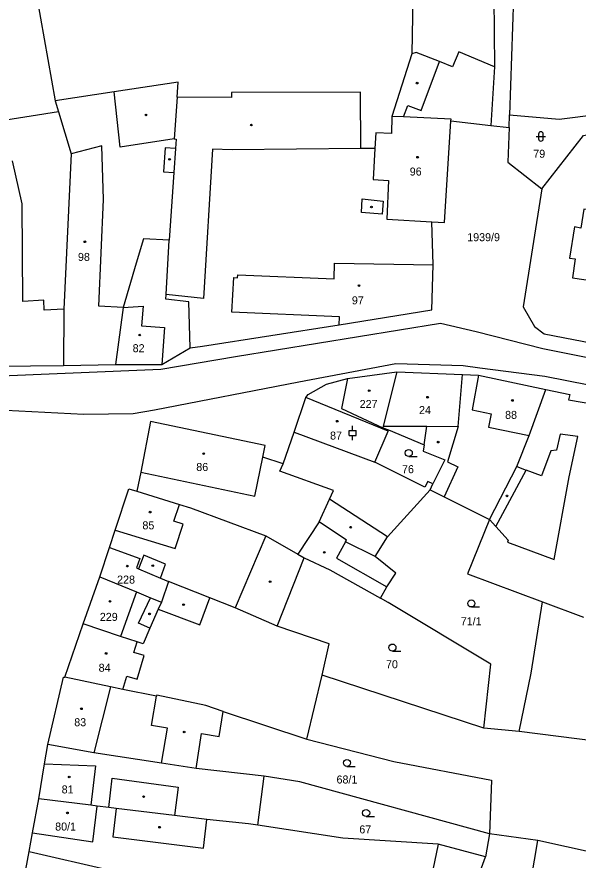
# Model space of a CAD drawing. Extents: x -794765 to -785424, y -1118958 to -1108731.
# Drawn here: x -788215.5 to -788096.4, y -1116478.9 to -1116299.9 of the extents above; entities that cross this region are included whole.
import ezdxf

# ---------------------------------------------------------------- set-up
doc = ezdxf.new("R2010")
doc.units = 0
for name, color, linetype in [('Level 66', 7, 'Continuous'), ('Level 75', 7, 'Continuous'), ('Level 76', 7, 'Continuous'), ('Level 77', 7, 'Continuous'), ('Level 79', 7, 'Continuous')]:
    doc.layers.add(name, color=color, linetype=linetype)

msp = doc.modelspace()

# ---------------------------------------------------------------- linework, layer by layer
at = {"layer": 'Level 66'}
for p, q in [((-788104.81, -1116324.75), (-788104.81, -1116325.75)), ((-788103.81, -1116325.75), (-788103.81, -1116324.75)), ((-788105.31, -1116325.25), (-788103.31, -1116325.25)), ((-788144.27, -1116387.72), (-788144.27, -1116386.72)), ((-788145.02, -1116387.72), (-788143.52, -1116387.72)), ((-788145.02, -1116388.72), (-788145.02, -1116387.72)), ((-788145.02, -1116388.72), (-788143.52, -1116388.72)), ((-788144.27, -1116389.72), (-788144.27, -1116388.72)), ((-788143.52, -1116388.72), (-788143.52, -1116387.72)), ((-788132.34, -1116393.21), (-788130.59, -1116393.21)), ((-788119.06, -1116425.15), (-788117.31, -1116425.15)), ((-788135.81, -1116434.52), (-788134.06, -1116434.52)), ((-788145.46, -1116459.02), (-788143.71, -1116459.02)), ((-788141.39, -1116469.65), (-788139.64, -1116469.65))]:
    msp.add_line(p, q, dxfattribs=at)
for centre in [(-788132.34, -1116392.46), (-788119.06, -1116424.4), (-788135.81, -1116433.77), (-788145.46, -1116458.27), (-788141.39, -1116468.9)]:
    msp.add_circle(centre, 0.75, dxfattribs=at)
for centre, start, end in [((-788104.31, -1116324.75), 0, 180), ((-788104.31, -1116325.75), 180, 359.9879)]:
    msp.add_arc(centre, 0.5, start, end, dxfattribs=at)
at = {"layer": 'Level 75'}
for p, q in [((-788109.43, -1116275.32), (-788110.98, -1116320.69)), ((-788214.62, -1116276.87), (-788207.41, -1116317.68)), ((-788131.16, -1116277.26), (-788131.71, -1116307.69)), ((-788114.43, -1116279.33), (-788114.17, -1116310.48)), ((-788114.17, -1116310.48), (-788114.92, -1116322.89)), ((-788207.41, -1116317.68), (-788206.71, -1116320.02)), ((-788206.71, -1116320.02), (-788223.3, -1116322.65)), ((-788111.07, -1116323.34), (-788110.98, -1116320.69)), ((-788114.92, -1116322.89), (-788111.07, -1116323.34)), ((-788222.28, -1116374.04), (-788205.6, -1116373.91)), ((-788205.6, -1116373.91), (-788194.63, -1116373.69)), ((-788134.88, -1116375.26), (-788120.97, -1116375.78)), ((-788136.75, -1116387.84), (-788154.18, -1116380.69)), ((-788136.75, -1116387.84), (-788136.64, -1116387.57)), ((-788136.64, -1116387.57), (-788129.09, -1116390.72)), ((-788127.83, -1116400.27), (-788127.21, -1116399.02)), ((-788197.94, -1116418.79), (-788195.87, -1116412.55)), ((-788160.3, -1116429.24), (-788154.54, -1116414.71)), ((-788201.48, -1116428.76), (-788197.94, -1116418.79)), ((-788183.36, -1116419.76), (-788184.84, -1116424.13)), ((-788103.93, -1116424.04), (-788095.26, -1116427.29)), ((-788205.35, -1116440.07), (-788201.48, -1116428.76)), ((-788153.97, -1116453.21), (-788150.71, -1116439.67)), ((-788116.43, -1116450.89), (-788150.71, -1116439.67)), ((-788171.76, -1116447.38), (-788153.97, -1116453.21)), ((-788108.88, -1116451.59), (-788116.43, -1116450.89)), ((-788070.15, -1116456.47), (-788108.88, -1116451.59)), ((-788163.01, -1116461.06), (-788177.5, -1116459.45)), ((-788164.41, -1116471.51), (-788163.01, -1116461.06)), ((-788115.24, -1116473.36), (-788116.05, -1116478.24)), ((-788104.94, -1116474.74), (-788115.24, -1116473.36)), ((-788109.95, -1116503.68), (-788104.94, -1116474.74)), ((-788116.05, -1116478.24), (-788126.07, -1116475.51)), ((-788120.85, -1116491.06), (-788116.05, -1116478.24))]:
    msp.add_line(p, q, dxfattribs=at)
for points in [[(-788131.71, -1116307.69), (-788135.94, -1116321), (-788135.99, -1116324.59), (-788139.33, -1116324.46), (-788139.53, -1116327.84)], [(-788114.17, -1116310.48), (-788121.75, -1116307.28), (-788123.04, -1116310.44), (-788125.79, -1116309.36), (-788130.81, -1116307.4), (-788131.71, -1116307.69)], [(-788181.52, -1116316.94), (-788181.29, -1116313.7), (-788194.86, -1116315.77), (-788207.41, -1116317.68)], [(-788181.52, -1116316.94), (-788182.17, -1116325.75), (-788181.73, -1116325.82), (-788181.87, -1116327.84), (-788182.21, -1116332.88), (-788183.18, -1116347.24)], [(-788139.53, -1116327.84), (-788142.54, -1116327.81), (-788142.59, -1116315.86), (-788169.99, -1116315.9), (-788169.98, -1116316.98), (-788181.52, -1116316.94)], [(-788206.71, -1116320.02), (-788204, -1116328.92), (-788205.54, -1116361.89), (-788205.6, -1116373.91)], [(-788110.98, -1116320.69), (-788100.4, -1116321.61), (-788083.57, -1116319.47), (-788043.34, -1116329.62), (-788043.51, -1116333.19)], [(-788127.43, -1116343.38), (-788124.74, -1116343.55), (-788123.4, -1116321.9), (-788114.92, -1116322.89)], [(-788104.08, -1116336.38), (-788095.27, -1116325.08), (-788084.6, -1116322.77), (-788075.84, -1116324.92), (-788043.51, -1116333.19)], [(-788111.07, -1116323.34), (-788111.32, -1116330.72), (-788104.08, -1116336.38)], [(-788139.53, -1116327.84), (-788139.9, -1116334.41), (-788136.65, -1116334.6), (-788137.01, -1116342.78), (-788127.43, -1116343.38)], [(-788104.08, -1116336.38), (-788108.05, -1116361.45), (-788105.63, -1116365.59), (-788103.61, -1116367.18), (-788046.1, -1116378.3), (-788038.81, -1116378.46), (-788035.35, -1116378.54), (-788022.85, -1116378.83), (-788020.59, -1116378.86)], [(-788065.34, -1116346.88), (-788064.86, -1116342.89), (-788072.76, -1116341.74), (-788073.06, -1116343.77), (-788095.19, -1116340.68), (-788095.84, -1116344.71), (-788097.16, -1116344.45), (-788098.21, -1116351.08), (-788097, -1116351.26), (-788097.58, -1116355.3), (-788075.44, -1116358.49), (-788075.73, -1116360.48), (-788067.47, -1116361.8), (-788066.97, -1116357.98)], [(-788178.72, -1116370.15), (-788176.14, -1116369.75), (-788147.1, -1116365.24), (-788127.46, -1116362.08), (-788127.18, -1116352.49), (-788127.43, -1116343.38)], [(-788183.18, -1116347.24), (-788188.64, -1116346.96), (-788190.2, -1116352.14), (-788192.99, -1116361.57), (-788194.63, -1116373.69)], [(-788178.72, -1116370.15), (-788179.03, -1116360.37), (-788183.89, -1116359.83), (-788183.83, -1116358.84), (-788183.18, -1116347.24)], [(-788279.68, -1116369.68), (-788255.51, -1116372.91), (-788222.27, -1116376.2), (-788184.96, -1116374.64), (-788169.09, -1116371.97), (-788125.59, -1116364.93), (-788118.03, -1116366.65), (-788103.88, -1116370.26), (-788071.66, -1116376.73), (-788047.19, -1116381.42), (-788037.25, -1116382.67), (-788028.44, -1116382.62), (-788012.56, -1116381.23), (-787982.57, -1116375.12), (-787957.81, -1116369.21), (-787938.9, -1116364.93), (-787918.57, -1116359.78), (-787902.51, -1116353.37)], [(-788194.63, -1116373.69), (-788184.79, -1116373.64), (-788178.72, -1116370.15)], [(-788014.95, -1116388.89), (-788036.64, -1116389.18), (-788070.79, -1116382.68), (-788103.44, -1116376.2), (-788117.24, -1116374.47), (-788120.83, -1116373.97), (-788135.12, -1116373.51), (-788155.68, -1116377.39), (-788186.34, -1116383.39), (-788190.87, -1116384.17), (-788201.33, -1116384.26), (-788234.5, -1116382.6)], [(-788154.18, -1116380.69), (-788153.72, -1116380.03), (-788149.81, -1116377.84), (-788145.34, -1116376.64), (-788134.88, -1116375.26)], [(-788134.88, -1116375.26), (-788137.77, -1116386.76), (-788137.87, -1116387.15), (-788136.64, -1116387.57)], [(-788129.09, -1116390.72), (-788128.51, -1116386.8), (-788121.84, -1116386.83), (-788120.97, -1116375.78)], [(-788120.97, -1116375.78), (-788117.53, -1116375.94), (-788103.27, -1116378.99)], [(-788115.23, -1116406.59), (-788109.4, -1116395.34), (-788106.8, -1116388.75), (-788103.27, -1116378.99)], [(-788103.27, -1116378.99), (-788098.18, -1116380.06), (-788098.42, -1116381.18), (-788087.66, -1116383.04)], [(-788158.98, -1116394.77), (-788156.67, -1116388.02), (-788154.18, -1116380.69)], [(-788158.98, -1116394.77), (-788163.35, -1116393.38), (-788162.84, -1116390.9), (-788187.15, -1116385.8), (-788189.24, -1116396.5), (-788190.04, -1116400.59)], [(-788127.21, -1116399.02), (-788128.28, -1116398.48), (-788128.93, -1116399.72), (-788139.57, -1116394.39), (-788136.75, -1116387.84)], [(-788129.09, -1116390.72), (-788129.29, -1116392.1), (-788124.69, -1116393.9), (-788127.21, -1116399.02)], [(-788139.45, -1116414.42), (-788145.74, -1116411.34), (-788145.55, -1116410.99), (-788151.37, -1116407.11), (-788149.16, -1116402.28), (-788148.33, -1116400.45), (-788159.73, -1116396.34), (-788158.98, -1116394.77)], [(-788195.87, -1116412.55), (-788194.66, -1116408.85), (-788191.79, -1116400.06), (-788190.04, -1116400.59)], [(-788190.04, -1116400.59), (-788181.01, -1116403.37), (-788178.69, -1116404.08), (-788162.65, -1116410.07), (-788155.88, -1116413.94), (-788154.54, -1116414.71)], [(-788139.45, -1116414.42), (-788136.88, -1116410.27), (-788127.83, -1116400.27)], [(-788127.83, -1116400.27), (-788124.8, -1116401.79), (-788115.23, -1116406.59)], [(-788115.23, -1116406.59), (-788119.86, -1116418.09), (-788103.93, -1116424.04)], [(-788195.87, -1116412.55), (-788189.44, -1116414.86), (-788190.15, -1116416.83), (-788189.69, -1116417.03), (-788185.06, -1116419.03), (-788183.36, -1116419.76)], [(-788154.54, -1116414.71), (-788149.09, -1116417.3), (-788138.38, -1116423.32)], [(-788138.38, -1116423.32), (-788137.02, -1116420.9), (-788135.06, -1116418.01), (-788139.45, -1116414.42)], [(-788197.94, -1116418.79), (-788190.17, -1116421.96), (-788187.16, -1116423.18), (-788184.84, -1116424.13)], [(-788160.3, -1116429.24), (-788169.18, -1116425.31), (-788174.6, -1116423.18), (-788183.36, -1116419.76)], [(-788184.84, -1116424.13), (-788185.51, -1116425.65), (-788187.28, -1116429.68), (-788188.73, -1116432.97), (-788189.99, -1116432.55), (-788193.51, -1116431.39), (-788201.48, -1116428.76)], [(-788116.43, -1116450.89), (-788114.93, -1116437.28), (-788136.74, -1116424.24), (-788138.38, -1116423.32)], [(-788108.88, -1116451.59), (-788106.39, -1116439.24), (-788103.93, -1116424.04)], [(-788150.71, -1116439.67), (-788149.21, -1116432.99), (-788160.3, -1116429.24)], [(-788208.95, -1116454.34), (-788205.6, -1116440.03), (-788205.35, -1116440.07)], [(-788171.76, -1116447.38), (-788175.45, -1116446.09), (-788185.85, -1116443.91), (-788185.88, -1116444.11), (-788193.02, -1116442.67), (-788195.64, -1116442.11), (-788205.35, -1116440.07)], [(-788177.5, -1116459.45), (-788176.32, -1116452.05), (-788172.6, -1116452.64), (-788171.76, -1116447.38)], [(-788153.97, -1116453.21), (-788135.51, -1116457.97), (-788114.8, -1116461.92), (-788115.24, -1116473.36)], [(-788210.89, -1116465.91), (-788209.64, -1116458.45), (-788208.95, -1116454.34)], [(-788177.5, -1116459.45), (-788184.83, -1116458.32), (-788199.21, -1116456.1), (-788208.95, -1116454.34)], [(-788115.24, -1116473.36), (-788155.5, -1116462.27), (-788163.01, -1116461.06)], [(-788212.93, -1116477.1), (-788212.2, -1116473.12), (-788210.89, -1116465.91)], [(-788164.41, -1116471.51), (-788166.38, -1116471.21), (-788175.2, -1116470.3), (-788182.05, -1116469.46), (-788194.43, -1116467.93), (-788196.03, -1116467.74), (-788198.47, -1116467.44), (-788199.85, -1116467.27), (-788210.89, -1116465.91)], [(-788126.07, -1116475.51), (-788146.31, -1116474.27), (-788164.41, -1116471.51)], [(-788052.25, -1116486.37), (-788061.11, -1116484.42), (-788104.94, -1116474.74)], [(-788126.07, -1116475.51), (-788128.71, -1116488.11), (-788120.85, -1116491.06)], [(-788212.73, -1116491.1), (-788214.3, -1116484.72), (-788212.93, -1116477.1)], [(-788212.93, -1116477.1), (-788195.76, -1116481.01), (-788171.85, -1116483.53)]]:
    msp.add_lwpolyline(points, dxfattribs=at)
at = {"layer": 'Level 77'}
for p, q in [((-788129.7, -1116319.76), (-788125.79, -1116309.36)), ((-788193.62, -1116327.51), (-788194.86, -1116315.77)), ((-788133.47, -1116321.09), (-788132.56, -1116318.69)), ((-788132.56, -1116318.69), (-788129.7, -1116319.76)), ((-788133.47, -1116321.09), (-788135.94, -1116321)), ((-788123.38, -1116321.58), (-788133.47, -1116321.09)), ((-788123.4, -1116321.9), (-788123.38, -1116321.58)), ((-788182.17, -1116325.75), (-788193.62, -1116327.51)), ((-788197.48, -1116327.27), (-788204, -1116328.92)), ((-788197.15, -1116338.67), (-788197.48, -1116327.27)), ((-788184.08, -1116327.69), (-788184.43, -1116332.73)), ((-788181.87, -1116327.84), (-788184.08, -1116327.69)), ((-788174.03, -1116327.95), (-788175.93, -1116359.64)), ((-788169.82, -1116328.06), (-788174.03, -1116327.95)), ((-788142.54, -1116327.81), (-788169.82, -1116328.06)), ((-788214.44, -1116339.57), (-788216.44, -1116330.4)), ((-788184.43, -1116332.73), (-788182.21, -1116332.88)), ((-788198.15, -1116361.3), (-788197.15, -1116338.67)), ((-788142.41, -1116341.39), (-788142.24, -1116338.46)), ((-788142.24, -1116338.46), (-788137.76, -1116338.96)), ((-788137.76, -1116338.96), (-788138, -1116341.78)), ((-788214.27, -1116360.27), (-788214.44, -1116339.57)), ((-788138, -1116341.78), (-788142.41, -1116341.39)), ((-788148.16, -1116355.5), (-788148.12, -1116352.17)), ((-788148.12, -1116352.17), (-788127.18, -1116352.49)), ((-788168.67, -1116355.28), (-788168.64, -1116354.65)), ((-788168.64, -1116354.65), (-788148.16, -1116355.5)), ((-788169.92, -1116362.58), (-788169.51, -1116355.23)), ((-788169.51, -1116355.23), (-788168.67, -1116355.28)), ((-788209.8, -1116360.02), (-788214.27, -1116360.27)), ((-788209.77, -1116362.11), (-788209.8, -1116360.02)), ((-788175.93, -1116359.64), (-788183.83, -1116358.84)), ((-788205.54, -1116361.89), (-788209.77, -1116362.11)), ((-788192.99, -1116361.57), (-788198.15, -1116361.3)), ((-788192.99, -1116361.57), (-788188.73, -1116361.26)), ((-788188.73, -1116361.26), (-788189.05, -1116365.48)), ((-788147.04, -1116363.56), (-788169.92, -1116362.58)), ((-788147.1, -1116365.24), (-788147.04, -1116363.56)), ((-788189.05, -1116365.48), (-788184.2, -1116365.85)), ((-788184.2, -1116365.85), (-788184.79, -1116373.64)), ((-788145.34, -1116376.64), (-788146.65, -1116383.02)), ((-788117.53, -1116375.94), (-788118.87, -1116383.33)), ((-788146.65, -1116383.02), (-788137.87, -1116387.15)), ((-788118.87, -1116383.33), (-788114.84, -1116384.17)), ((-788114.84, -1116384.17), (-788115.42, -1116386.97)), ((-788137.77, -1116386.76), (-788128.51, -1116386.8)), ((-788121.84, -1116386.83), (-788124.12, -1116394.33)), ((-788115.42, -1116386.97), (-788106.8, -1116388.75)), ((-788156.67, -1116388.02), (-788139.57, -1116394.39)), ((-788100.18, -1116388.44), (-788101, -1116391.85)), ((-788096.44, -1116388.94), (-788100.18, -1116388.44)), ((-788098.28, -1116397.51), (-788096.44, -1116388.94)), ((-788102.18, -1116391.98), (-788104.18, -1116397.28)), ((-788101, -1116391.85), (-788102.18, -1116391.98)), ((-788165.05, -1116401.64), (-788163.35, -1116393.38)), ((-788124.12, -1116394.33), (-788121.93, -1116395.41)), ((-788121.93, -1116395.41), (-788124.8, -1116401.79)), ((-788113.88, -1116408.09), (-788107.42, -1116396.08)), ((-788109.4, -1116395.34), (-788107.42, -1116396.08)), ((-788104.18, -1116397.28), (-788107.42, -1116396.08)), ((-788189.24, -1116396.5), (-788165.05, -1116401.64)), ((-788101.48, -1116415.07), (-788098.28, -1116397.51)), ((-788182.19, -1116406.95), (-788181.01, -1116403.37)), ((-788136.88, -1116410.27), (-788149.16, -1116402.28)), ((-788180.23, -1116407.6), (-788182.19, -1116406.95)), ((-788151.37, -1116407.11), (-788155.88, -1116413.94)), ((-788113.88, -1116408.09), (-788115.23, -1116406.59)), ((-788194.66, -1116408.85), (-788181.92, -1116412.73)), ((-788181.92, -1116412.73), (-788180.23, -1116407.6)), ((-788113.88, -1116408.09), (-788111.27, -1116410.99)), ((-788162.65, -1116410.07), (-788169.18, -1116425.31)), ((-788145.74, -1116411.34), (-788147.69, -1116414.79)), ((-788111.27, -1116410.99), (-788111.42, -1116411.41)), ((-788111.42, -1116411.41), (-788101.48, -1116415.07)), ((-788188.61, -1116414.14), (-788189.69, -1116417.03)), ((-788183.99, -1116416.1), (-788188.61, -1116414.14)), ((-788147.69, -1116414.79), (-788137.02, -1116420.9)), ((-788185.06, -1116419.03), (-788183.99, -1116416.1)), ((-788190.17, -1116421.96), (-788193.51, -1116431.39)), ((-788189.68, -1116428.62), (-788187.16, -1116423.18)), ((-788176.67, -1116428.98), (-788174.6, -1116423.18)), ((-788185.51, -1116425.65), (-788176.67, -1116428.98)), ((-788187.28, -1116429.68), (-788189.68, -1116428.62)), ((-788190.68, -1116434.84), (-788189.99, -1116432.55)), ((-788188.52, -1116435.48), (-788190.68, -1116434.84)), ((-788190, -1116440.48), (-788188.52, -1116435.48)), ((-788193.02, -1116442.67), (-788192.17, -1116439.83)), ((-788192.17, -1116439.83), (-788190, -1116440.48)), ((-788195.64, -1116442.11), (-788199.21, -1116456.1)), ((-788186.94, -1116450.32), (-788185.88, -1116444.11)), ((-788183.57, -1116450.9), (-788186.94, -1116450.32)), ((-788184.83, -1116458.32), (-788183.57, -1116450.9)), ((-788209.64, -1116458.45), (-788198.83, -1116458.9)), ((-788198.83, -1116458.9), (-788199.85, -1116467.27)), ((-788196.03, -1116467.74), (-788195.27, -1116461.51)), ((-788195.27, -1116461.51), (-788181.31, -1116463.43)), ((-788181.31, -1116463.43), (-788182.05, -1116469.46)), ((-788199.4, -1116475.03), (-788198.47, -1116467.44)), ((-788194.43, -1116467.93), (-788195.17, -1116473.99)), ((-788175.94, -1116476.35), (-788175.2, -1116470.3)), ((-788212.2, -1116473.12), (-788199.4, -1116475.03)), ((-788195.17, -1116473.99), (-788175.94, -1116476.35))]:
    msp.add_line(p, q, dxfattribs=at)
at = {"layer": 'Level 79'}
for centre in [(-788130.57, -1116313.93), (-788188.13, -1116320.69), (-788165.75, -1116322.82), (-788183.13, -1116330.1), (-788130.48, -1116329.65), (-788140.27, -1116340.23), (-788201.1, -1116347.61), (-788142.92, -1116356.9), (-788189.45, -1116367.42), (-788140.74, -1116379.24), (-788128.36, -1116380.62), (-788110.34, -1116381.31), (-788147.54, -1116385.72), (-788126.1, -1116390.15), (-788175.88, -1116392.6), (-788111.5, -1116401.57), (-788187.24, -1116405.02), (-788144.67, -1116408.22), (-788150.28, -1116413.57), (-788192.09, -1116416.48), (-788186.68, -1116416.39), (-788161.77, -1116419.78), (-788195.76, -1116423.97), (-788180.15, -1116424.67), (-788187.37, -1116426.62), (-788196.58, -1116435.02), (-788201.82, -1116446.77), (-788180.02, -1116451.72), (-788204.42, -1116461.25), (-788188.62, -1116465.42), (-788204.8, -1116468.87), (-788185.25, -1116471.92)]:
    msp.add_circle(centre, 0.175, dxfattribs=at)

# ---------------------------------------------------------------- texts
at = {"layer": 'Level 76'}
for s, p in [('79', (-788105.92, -1116329.77)), ('96', (-788132.14, -1116333.55)), ('1939/9', (-788119.94, -1116347.49)), ('98', (-788202.56, -1116351.68)), ('97', (-788144.42, -1116360.9)), ('82', (-788190.95, -1116371.06)), ('227', (-788142.77, -1116382.9)), ('24', (-788130.17, -1116384.19)), ('88', (-788111.9, -1116385.22)), ('87', (-788149.05, -1116389.61)), ('86', (-788177.45, -1116396.28)), ('76', (-788133.78, -1116396.75)), ('85', (-788188.88, -1116408.67)), ('228', (-788194.25, -1116420.19)), ('229', (-788197.92, -1116428.11)), ('71/1', (-788121.31, -1116429.04)), ('84', (-788198.18, -1116438.91)), ('70', (-788137.18, -1116438.17)), ('83', (-788203.35, -1116450.48)), ('68/1', (-788147.68, -1116462.64)), ('81', (-788206.02, -1116464.75)), ('80/1', (-788207.4, -1116472.63)), ('67', (-788142.84, -1116473.24))]:
    msp.add_text(s, height=1.7, dxfattribs=at).set_placement(p)

doc.saveas('drawing.dxf')
